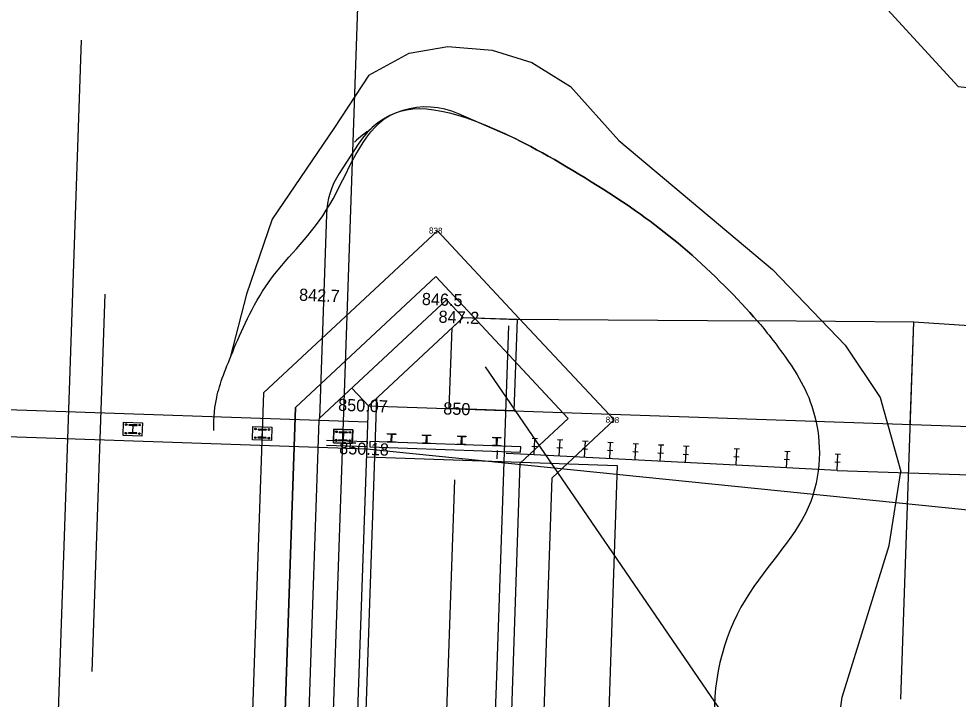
# Model space of a CAD drawing. Extents: x 2191309 to 2193046, y 863659 to 865133.
# Drawn here: x 2192668.4 to 2192726.5, y 863927.7 to 863969.7 of the extents above; entities that cross this region are included whole.
import ezdxf

# ---------------------------------------------------------------- set-up
doc = ezdxf.new("R2010")
doc.units = 0
for name, color, linetype in [('D_Bridge_Abutment', 7, 'Continuous'), ('D_Bridge_Deck', 7, 'Continuous'), ('D_Bridge_Railing', 7, 'Continuous'), ('D_Bridge_Substructure_Hidden', 7, 'Continuous'), ('D_Guardrail_Beam_Lt', 7, 'Continuous'), ('D_Roadway_Edge_Shoulder', 7, 'Continuous'), ('D_Roadway_Edge_TW', 7, 'Continuous'), ('D_Slope_ClearingLimitLine', 7, 'Continuous'), ('D_Slope_Direction', 7, 'Continuous'), ('D_Slope_Toe', 7, 'Continuous'), ('DIMENSIONS', 7, 'Continuous'), ('JUNK', 7, 'Continuous')]:
    doc.layers.add(name, color=color, linetype=linetype)

msp = doc.modelspace()

# ---------------------------------------------------------------- linework, layer by layer
at = {"layer": 'D_Bridge_Abutment'}
for p, q in [((2192699.084, 863962.305), (2192695.589, 863963.839)), ((2192689.376, 863961.967), (2192688.21, 863960.156)), ((2192687.417, 863957.62), (2192686.984, 863945.016)), ((2192686.984, 863945.016), (2192694.836, 863952.347)), ((2192686.984, 863945.016), (2192694.836, 863952.347)), ((2192695.86, 863951.251), (2192694.836, 863952.347)), ((2192694.836, 863952.347), (2192695.86, 863951.251)), ((2192690.012, 863945.791), (2192695.86, 863951.251)), ((2192695.86, 863951.251), (2192698.701, 863951.153)), ((2192698.701, 863951.153), (2192714.042, 863951.037)), ((2192698.701, 863951.153), (2192714.042, 863951.037)), ((2192690.012, 863945.791), (2192688.989, 863946.888)), ((2192688.846, 863911.811), (2192690.012, 863945.791)), ((2192686.98, 863944.895), (2192686.984, 863945.016))]:
    msp.add_line(p, q, dxfattribs=at)
for centre, start, end in [((2192693.58, 863959.26), 66.31376, 147.21624), ((2192692.414, 863957.449), 147.21624, 178.03426)]:
    msp.add_arc(centre, 5, start, end, dxfattribs=at)
msp.add_open_spline([(2192714.042, 863951.037), (2192712.874, 863952.402), (2192709.641, 863955.623), (2192705.292, 863958.801), (2192700.703, 863961.518), (2192699.084, 863962.305)], degree=3, dxfattribs=at)
at = {"layer": 'D_Bridge_Deck'}
for p, q in [((2192653, 863946.061), (2192689.978, 863944.792)), ((2192652.943, 863944.395), (2192689.921, 863943.126))]:
    msp.add_line(p, q, dxfattribs=at)
at = {"layer": 'D_Bridge_Railing'}
for p, q in [((2192675.208, 863944.621), (2192675.207, 863944.585)), ((2192675.207, 863944.585), (2192675.418, 863944.577)), ((2192675.718, 863944.604), (2192675.208, 863944.621)), ((2192675.506, 863944.574), (2192675.717, 863944.567)), ((2192675.717, 863944.567), (2192675.718, 863944.604)), ((2192675.191, 863944.127), (2192675.19, 863944.09)), ((2192675.19, 863944.09), (2192675.7, 863944.073)), ((2192675.403, 863944.119), (2192675.191, 863944.127)), ((2192675.448, 863944.545), (2192675.434, 863944.149)), ((2192675.46, 863944.148), (2192675.474, 863944.545)), ((2192675.701, 863944.109), (2192675.49, 863944.116)), ((2192675.7, 863944.073), (2192675.701, 863944.109)), ((2192683.204, 863944.347), (2192683.202, 863944.31)), ((2192683.202, 863944.31), (2192683.414, 863944.303)), ((2192683.714, 863944.329), (2192683.204, 863944.347)), ((2192683.443, 863944.271), (2192683.43, 863943.875)), ((2192683.456, 863943.874), (2192683.469, 863944.27)), ((2192683.501, 863944.3), (2192683.712, 863944.293)), ((2192683.712, 863944.293), (2192683.714, 863944.329)), ((2192688.201, 863944.175), (2192688.199, 863944.139)), ((2192688.199, 863944.139), (2192688.411, 863944.131)), ((2192688.201, 863944.138), (2192688.203, 863944.175)), ((2192688.711, 863944.158), (2192688.201, 863944.175)), ((2192688.411, 863944.13), (2192688.201, 863944.138)), ((2192688.203, 863944.175), (2192688.709, 863944.158)), ((2192688.426, 863943.704), (2192688.44, 863944.1)), ((2192688.44, 863944.1), (2192688.427, 863943.703)), ((2192688.467, 863944.099), (2192688.453, 863943.703)), ((2192688.453, 863943.702), (2192688.466, 863944.099)), ((2192688.708, 863944.12), (2192688.497, 863944.127)), ((2192688.498, 863944.128), (2192688.709, 863944.121)), ((2192688.709, 863944.158), (2192688.708, 863944.12)), ((2192688.709, 863944.121), (2192688.711, 863944.158)), ((2192691.199, 863944.035), (2192691.201, 863944.073)), ((2192691.41, 863944.027), (2192691.199, 863944.035)), ((2192691.201, 863944.073), (2192691.707, 863944.055)), ((2192691.425, 863943.601), (2192691.438, 863943.997)), ((2192691.465, 863943.996), (2192691.451, 863943.6)), ((2192691.706, 863944.017), (2192691.496, 863944.024)), ((2192691.707, 863944.055), (2192691.706, 863944.017)), ((2192693.365, 863943.96), (2192693.366, 863943.998)), ((2192693.366, 863943.998), (2192693.872, 863943.981)), ((2192683.187, 863943.852), (2192683.185, 863943.816)), ((2192683.185, 863943.816), (2192683.695, 863943.798)), ((2192683.398, 863943.845), (2192683.187, 863943.852)), ((2192683.697, 863943.835), (2192683.485, 863943.842)), ((2192683.695, 863943.798), (2192683.697, 863943.835)), ((2192688.184, 863943.681), (2192688.182, 863943.644)), ((2192688.182, 863943.644), (2192688.693, 863943.627)), ((2192688.184, 863943.644), (2192688.186, 863943.682)), ((2192688.395, 863943.673), (2192688.184, 863943.681)), ((2192688.691, 863943.627), (2192688.184, 863943.644)), ((2192688.186, 863943.682), (2192688.396, 863943.675)), ((2192688.482, 863943.672), (2192688.692, 863943.665)), ((2192688.694, 863943.663), (2192688.483, 863943.67)), ((2192688.692, 863943.665), (2192688.691, 863943.627)), ((2192688.693, 863943.627), (2192688.694, 863943.663)), ((2192691.182, 863943.541), (2192691.184, 863943.579)), ((2192691.689, 863943.524), (2192691.182, 863943.541)), ((2192691.184, 863943.579), (2192691.394, 863943.572)), ((2192691.48, 863943.569), (2192691.69, 863943.562)), ((2192691.69, 863943.562), (2192691.689, 863943.524)), ((2192693.348, 863943.467), (2192693.349, 863943.505)), ((2192693.854, 863943.45), (2192693.348, 863943.467)), ((2192693.349, 863943.505), (2192693.559, 863943.498)), ((2192693.575, 863943.953), (2192693.365, 863943.96)), ((2192693.59, 863943.526), (2192693.604, 863943.922)), ((2192693.63, 863943.921), (2192693.617, 863943.525)), ((2192693.645, 863943.495), (2192693.856, 863943.487)), ((2192693.871, 863943.943), (2192693.661, 863943.95)), ((2192693.856, 863943.487), (2192693.854, 863943.45)), ((2192693.872, 863943.981), (2192693.871, 863943.943)), ((2192695.513, 863943.393), (2192695.515, 863943.43)), ((2192695.515, 863943.43), (2192695.725, 863943.423)), ((2192695.53, 863943.886), (2192695.532, 863943.924)), ((2192695.74, 863943.879), (2192695.53, 863943.886)), ((2192695.532, 863943.924), (2192696.038, 863943.907)), ((2192695.755, 863943.452), (2192695.769, 863943.848)), ((2192695.796, 863943.847), (2192695.782, 863943.451)), ((2192695.811, 863943.42), (2192696.021, 863943.413)), ((2192696.037, 863943.869), (2192695.827, 863943.876)), ((2192696.021, 863943.413), (2192696.02, 863943.375)), ((2192696.038, 863943.907), (2192696.037, 863943.869)), ((2192697.696, 863943.812), (2192697.697, 863943.85)), ((2192697.906, 863943.804), (2192697.696, 863943.812)), ((2192697.697, 863943.85), (2192698.203, 863943.832)), ((2192697.921, 863943.378), (2192697.934, 863943.774)), ((2192697.961, 863943.773), (2192697.948, 863943.377)), ((2192698.202, 863943.794), (2192697.992, 863943.802)), ((2192698.203, 863943.832), (2192698.202, 863943.794)), ((2192696.02, 863943.375), (2192695.513, 863943.393)), ((2192697.679, 863943.318), (2192697.68, 863943.356)), ((2192698.185, 863943.301), (2192697.679, 863943.318)), ((2192697.68, 863943.356), (2192697.89, 863943.349)), ((2192697.976, 863943.346), (2192698.186, 863943.339)), ((2192698.186, 863943.339), (2192698.185, 863943.301))]:
    msp.add_line(p, q, dxfattribs=at)
for points in [[(2192674.886, 863944.783), (2192676.051, 863944.743), (2192676.023, 863943.91), (2192674.857, 863943.95)], [(2192682.881, 863944.509), (2192684.047, 863944.469), (2192684.018, 863943.636), (2192682.852, 863943.676)], [(2192687.878, 863944.337), (2192689.044, 863944.297), (2192689.015, 863943.464), (2192687.849, 863943.504)]]:
    msp.add_lwpolyline(points, close=True, dxfattribs=at)
for points in [[(2192689.02, 863943.615), (2192689.044, 863944.297), (2192687.878, 863944.337), (2192687.854, 863943.655)], [(2192687.432, 863943.67), (2192689.937, 863943.584), (2192689.925, 863943.251), (2192687.421, 863943.337)], [(2192687.854, 863943.655), (2192687.849, 863943.504), (2192689.015, 863943.464), (2192689.02, 863943.615)], [(2192699.431, 863943.258), (2192690.103, 863943.578), (2192690.092, 863943.245), (2192699.42, 863942.925), (2192699.431, 863943.258)]]:
    msp.add_lwpolyline(points, dxfattribs=at)
for centre in [(2192675.047, 863944.627), (2192675.88, 863944.598), (2192675.029, 863944.096), (2192675.862, 863944.067), (2192683.042, 863944.352), (2192683.875, 863944.324), (2192688.039, 863944.181), (2192688.039, 863944.181), (2192688.872, 863944.152), (2192688.872, 863944.152), (2192683.024, 863943.821), (2192683.857, 863943.793), (2192688.021, 863943.65), (2192688.854, 863943.621)]:
    msp.add_circle(centre, 0.0521, dxfattribs=at)
for centre, radius, start, end in [((2192675.417, 863944.547), 0.0308, 358.03426, 88.03426), ((2192675.505, 863944.544), 0.0308, 88.03426, 178.03426), ((2192675.404, 863944.15), 0.0308, 268.03426, 358.03426), ((2192675.491, 863944.147), 0.0308, 178.03426, 268.03426), ((2192683.412, 863944.272), 0.0308, 358.03426, 88.03426), ((2192683.5, 863944.269), 0.0308, 88.03426, 178.03426), ((2192688.41, 863944.101), 0.0308, 358.03426, 88.03426), ((2192688.41, 863944.101), 0.0298, 358.03426, 88.03426), ((2192688.497, 863944.098), 0.0308, 88.03426, 178.03426), ((2192688.496, 863944.098), 0.0298, 88.03426, 178.03426), ((2192691.408, 863943.998), 0.0298, 358.03426, 88.03426), ((2192691.495, 863943.995), 0.0298, 88.03426, 178.03426), ((2192683.399, 863943.876), 0.0308, 268.03426, 358.03426), ((2192683.487, 863943.873), 0.0308, 178.03426, 268.03426), ((2192688.396, 863943.704), 0.0308, 268.03426, 358.03426), ((2192688.397, 863943.705), 0.0298, 268.03426, 358.03426), ((2192688.483, 863943.702), 0.0298, 178.03426, 268.03426), ((2192688.484, 863943.701), 0.0308, 178.03426, 268.03426), ((2192691.395, 863943.602), 0.0298, 268.03426, 358.03426), ((2192691.481, 863943.599), 0.0298, 178.03426, 268.03426), ((2192693.56, 863943.527), 0.0298, 268.03426, 358.03426), ((2192693.574, 863943.923), 0.0298, 358.03426, 88.03426), ((2192693.646, 863943.524), 0.0298, 178.03426, 268.03426), ((2192693.66, 863943.92), 0.0298, 88.03426, 178.03426), ((2192695.726, 863943.453), 0.0298, 268.03426, 358.03426), ((2192695.739, 863943.849), 0.0298, 358.03426, 88.03426), ((2192695.812, 863943.45), 0.0298, 178.03426, 268.03426), ((2192695.825, 863943.846), 0.0298, 88.03426, 178.03426), ((2192697.905, 863943.775), 0.0298, 358.03426, 88.03426), ((2192697.991, 863943.772), 0.0298, 88.03426, 178.03426), ((2192697.891, 863943.379), 0.0298, 268.03426, 358.03426), ((2192697.977, 863943.376), 0.0298, 178.03426, 268.03426)]:
    msp.add_arc(centre, radius, start, end, dxfattribs=at)
at = {"layer": 'D_Bridge_Substructure_Hidden'}
for p, q in [((2192685.506, 863945.688), (2192694.178, 863953.785)), ((2192702.367, 863945.013), (2192694.178, 863953.785)), ((2192689.329, 863911.294), (2192690.529, 863946.274)), ((2192684.394, 863913.298), (2192685.506, 863945.688)), ((2192685.894, 863913.247), (2192686.98, 863944.895)), ((2192699.396, 863942.239), (2192702.367, 863945.013)), ((2192689.904, 863942.626), (2192705.395, 863942.095)), ((2192698.451, 863914.711), (2192699.396, 863942.239)), ((2192705.395, 863942.095), (2192704.446, 863914.444))]:
    msp.add_line(p, q, dxfattribs=at)
at = {"layer": 'D_Guardrail_Beam_Lt'}
for p, q in [((2192700.465, 863943.748), (2192700.132, 863943.765)), ((2192700.247, 863942.757), (2192700.299, 863943.756)), ((2192702.026, 863943.667), (2192701.693, 863943.685)), ((2192701.808, 863942.677), (2192701.859, 863943.676)), ((2192703.586, 863943.587), (2192703.253, 863943.604)), ((2192703.368, 863942.597), (2192703.42, 863943.596)), ((2192705.147, 863943.507), (2192704.814, 863943.524)), ((2192704.929, 863942.517), (2192704.98, 863943.516)), ((2192706.707, 863943.427), (2192706.374, 863943.444)), ((2192706.489, 863942.437), (2192706.541, 863943.435)), ((2192699.415, 863942.8), (2192698.52, 863942.831)), ((2192700.44, 863943.248), (2192700.107, 863943.265)), ((2192702, 863943.168), (2192701.667, 863943.185)), ((2192703.56, 863943.088), (2192703.228, 863943.105)), ((2192705.121, 863943.008), (2192704.788, 863943.025)), ((2192706.681, 863942.928), (2192706.348, 863942.945)), ((2192708.242, 863942.847), (2192707.909, 863942.865)), ((2192708.267, 863943.347), (2192707.935, 863943.364)), ((2192708.05, 863942.357), (2192708.101, 863943.355)), ((2192709.828, 863943.267), (2192709.495, 863943.284)), ((2192709.61, 863942.276), (2192709.661, 863943.275)), ((2192712.949, 863943.106), (2192712.616, 863943.123)), ((2192712.731, 863942.116), (2192712.782, 863943.115)), ((2192716.07, 863942.946), (2192715.737, 863942.963)), ((2192715.852, 863941.956), (2192715.903, 863942.954)), ((2192700.247, 863942.757), (2192699.415, 863942.8)), ((2192712.731, 863942.116), (2192700.247, 863942.757)), ((2192709.802, 863942.767), (2192709.469, 863942.784)), ((2192712.923, 863942.607), (2192712.59, 863942.624)), ((2192716.044, 863942.447), (2192715.711, 863942.464)), ((2192719.165, 863942.286), (2192718.832, 863942.303)), ((2192719.191, 863942.786), (2192718.858, 863942.803)), ((2192718.973, 863941.795), (2192719.024, 863942.794)), ((2192718.973, 863941.795), (2192712.731, 863942.116)), ((2192718.973, 863941.795), (2192747.917, 863940.802))]:
    msp.add_line(p, q, dxfattribs=at)
for centre, start, end in [((2192688.021, 863943.65), 358.03426, 178.03426), ((2192688.021, 863943.65), 178.03426, 358.03426), ((2192688.854, 863943.621), 358.03426, 178.03426), ((2192688.854, 863943.621), 178.03426, 358.03426)]:
    msp.add_arc(centre, 0.0521, start, end, dxfattribs=at)
at = {"layer": 'D_Roadway_Edge_Shoulder'}
msp.add_line((2192690.012, 863945.791), (2192748.02, 863943.8), dxfattribs=at)
at = {"layer": 'D_Roadway_Edge_TW'}
msp.add_lwpolyline([(2192689.921, 863943.126), (2192739.666, 863938.083), (2192747.828, 863937.803)], dxfattribs=at)
at = {"layer": 'D_Slope_ClearingLimitLine'}
msp.add_line((2192726.461, 863965.527), (2192751.394, 863962.646), dxfattribs=at)
msp.add_lwpolyline([(2192640.301, 863970.263), (2192661.289, 863990.353), (2192705.075, 863988.85), (2192726.461, 863965.527)], dxfattribs=at)
at = {"layer": 'D_Slope_Direction'}
msp.add_line((2192723.493, 863944.642), (2192723.71, 863950.964), dxfattribs=at)
at = {"layer": 'D_Slope_Toe'}
msp.add_lwpolyline([(2192863.161, 863939.558), (2192844.233, 863944.544), (2192833.832, 863946.693), (2192823.463, 863949.007), (2192809.16, 863951.791), (2192778.469, 863946.054), (2192773.378, 863946.179), (2192748.386, 863946.792), (2192741.14, 863949.813), (2192723.71, 863950.964), (2192714.042, 863951.037)], dxfattribs=at)
msp.add_lwpolyline([(2192695.181, 863950.617), (2192695.86, 863951.251), (2192699.202, 863951.149), (2192699.007, 863945.482), (2192695.009, 863945.62)], close=True, dxfattribs=at)
msp.add_open_spline([(2192699.084, 863962.305), (2192700.703, 863961.518), (2192705.292, 863958.801), (2192709.641, 863955.623), (2192712.874, 863952.402), (2192714.042, 863951.037)], degree=3, dxfattribs=at)
at = {"layer": 'DIMENSIONS'}
for p, q in [((2192687.137, 863905.744), (2192690.356, 863999.536)), ((2192753.012, 863866.823), (2192697.244, 863948.19))]:
    msp.add_line(p, q, dxfattribs=at)
at = {"layer": 'JUNK'}
for p, q in [((2192670.147, 863906.327), (2192672.277, 863968.379)), ((2192694.275, 863956.612), (2192683.536, 863946.585)), ((2192699.052, 863951.495), (2192694.275, 863956.612)), ((2192694.178, 863953.785), (2192685.506, 863945.688)), ((2192672.939, 863929.367), (2192673.739, 863952.679)), ((2192705.194, 863944.916), (2192699.052, 863951.495)), ((2192722.909, 863927.652), (2192723.71, 863950.964)), ((2192697.924, 863928.51), (2192698.687, 863950.727)), ((2192683.536, 863946.585), (2192682.33, 863911.463)), ((2192685.506, 863945.688), (2192684.358, 863912.223)), ((2192701.366, 863941.343), (2192705.194, 863944.916)), ((2192697.967, 863942.516), (2192697.984, 863943.016)), ((2192694.494, 863916.019), (2192695.358, 863941.206)), ((2192700.478, 863915.471), (2192701.366, 863941.343)), ((2192697.147, 863905.866), (2192697.924, 863928.51))]:
    msp.add_line(p, q, dxfattribs=at)
for points in [[(2192690.046, 863966.222), (2192692.529, 863967.591), (2192694.925, 863967.99), (2192697.655, 863967.771), (2192700.116, 863967.017), (2192702.501, 863965.517), (2192705.481, 863962.192), (2192714.977, 863954.22), (2192719.466, 863949.531), (2192721.635, 863946.308), (2192722.909, 863941.723)], [(2192690.046, 863966.222), (2192687.927, 863962.997), (2192684.06, 863957.335), (2192682.484, 863952.686), (2192681.478, 863948.768)], [(2192700.907, 863888.185), (2192710.351, 863894.547), (2192714.819, 863897.982), (2192718.745, 863902.331), (2192721.192, 863907.418), (2192721.778, 863911.717), (2192721.411, 863916.403), (2192720.124, 863918.666), (2192719.425, 863920.225), (2192718.977, 863922.395), (2192718.783, 863924.044), (2192719.287, 863927.776), (2192720.883, 863932.894), (2192722.2, 863937.154), (2192722.909, 863941.723)]]:
    msp.add_lwpolyline(points, dxfattribs=at)
msp.add_arc((2192694.275, 863956.612), 7.5, 122.98312, 133.03426, dxfattribs=at)
for points in [[(2192680.454, 863944.269), (2192680.455, 863944.679), (2192680.457, 863946.234), (2192681.56, 863949.024), (2192683.676, 863953.881), (2192687.91, 863957.524), (2192690.438, 863965.368), (2192695.598, 863964.001), (2192699.084, 863962.305)], [(2192714.042, 863951.037), (2192714.546, 863950.448), (2192715.819, 863948.853), (2192718.033, 863945.378), (2192718.005, 863938.963), (2192712.045, 863933.513), (2192710.6, 863924.308), (2192715.126, 863916.992), (2192716.664, 863905.894), (2192708.759, 863897.065), (2192700.367, 863890.385), (2192692.486, 863887.826), (2192685.832, 863890.057), (2192683.087, 863893.445), (2192682.032, 863895.929), (2192682.445, 863897.338), (2192682.626, 863897.958)]]:
    msp.add_open_spline(points, degree=3, dxfattribs=at)

# ---------------------------------------------------------------- texts
for s, height, p in [('838', 0.375, (2192693.749, 863956.442)), ('842.7', 0.75, (2192685.721, 863952.285)), ('846.5', 0.75, (2192693.309, 863952.024)), ('847.2', 0.75, (2192694.339, 863950.928)), ('850.07', 0.75, (2192688.134, 863945.48)), ('850', 0.75, (2192694.63, 863945.258)), ('838', 0.375, (2192704.668, 863944.747)), ('850.18', 0.75, (2192688.2, 863942.81))]:
    msp.add_text(s, height=height, rotation=358.03426, dxfattribs=at).set_placement(p)

doc.saveas('drawing.dxf')
